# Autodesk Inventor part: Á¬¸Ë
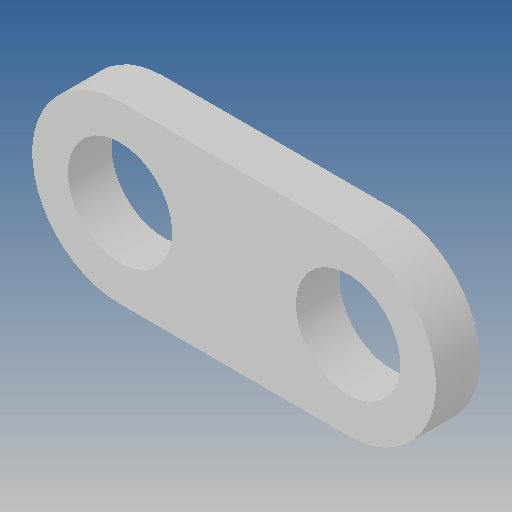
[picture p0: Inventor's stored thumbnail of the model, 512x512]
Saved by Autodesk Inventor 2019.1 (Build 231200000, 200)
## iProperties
Created: 2012-10
Part Number: Á¬¸Ë
Material: Ogólny
Document SubType Name: Modeling
Designer: CADENGINEERING4
Density: 1 g/cm^3
Appearance: Domyślna
Author: CADENGINEERING4
Revision Number: ÈÎºÎ
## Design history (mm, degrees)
feature "À­Éì1"
node "Bryła1"
